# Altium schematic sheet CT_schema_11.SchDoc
size 281 x 153 mm
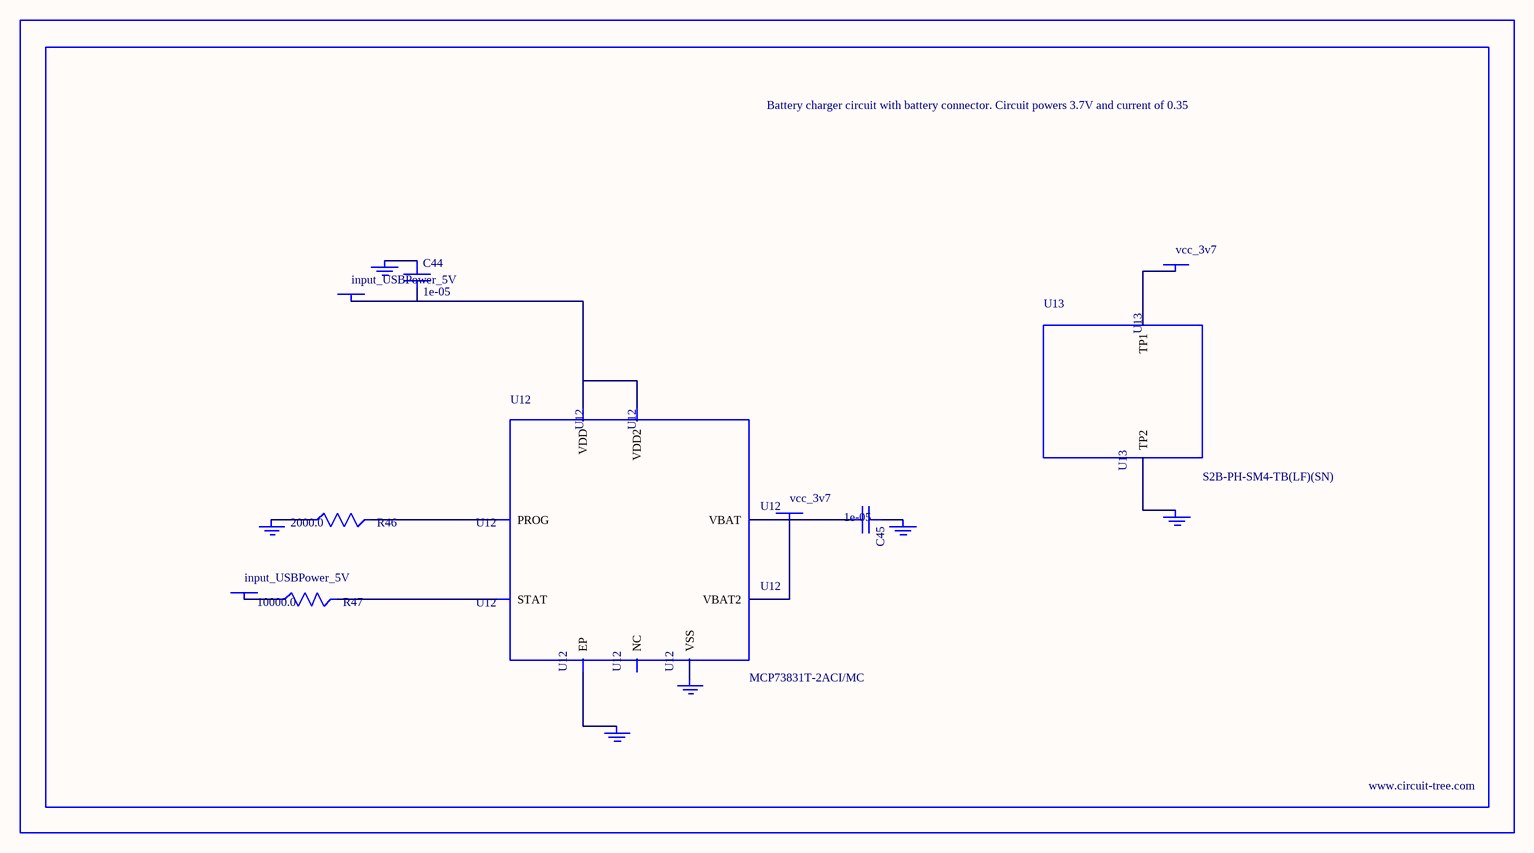
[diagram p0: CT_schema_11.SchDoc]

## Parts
BORDER10  (no value)
C44  1e-05  [C1206]
C45  1e-05  [C1206]
GND_INSTANCE_10_0  (no value)
GND_INSTANCE_10_1  (no value)
GND_INSTANCE_10_2  (no value)
GND_INSTANCE_10_3  (no value)
GND_INSTANCE_10_4  (no value)
GND_INSTANCE_10_5  (no value)
POWER_INSTANCE_10_0  input_USBPower_5V
POWER_INSTANCE_10_1  input_USBPower_5V
POWER_INSTANCE_10_2  vcc_3v7
POWER_INSTANCE_10_3  vcc_3v7
R46  2000.0  [R0603]
R47  10000.0  [R0603]
U12  MCP73831T-2ACI/MC  [DFN8_2X3MC]
U13  S2B-PH-SM4-TB(LF)(SN)  [JST-2-SMD]

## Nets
NetC44_1: C44.1 GND_INSTANCE_10_0.0(GND)
NetC44_2: C44.2 POWER_INSTANCE_10_0.0(PWR) U12.1(VDD) U12.2(VDD2)
NetC45_1: C45.1 GND_INSTANCE_10_1.0(GND)
NetC45_2: C45.2 POWER_INSTANCE_10_2.0(PWR) U12.3(VBAT) U12.4(VBAT2)
NetGND_INSTANCE_10_2_0: GND_INSTANCE_10_2.0(GND) R46.1
NetGND_INSTANCE_10_3_0: GND_INSTANCE_10_3.0(GND) U12.9(EP)
NetGND_INSTANCE_10_4_0: GND_INSTANCE_10_4.0(GND) U12.6(VSS)
NetGND_INSTANCE_10_5_0: GND_INSTANCE_10_5.0(GND) U13.2(TP2)
NetPOWER_INSTANCE_10_1_0: POWER_INSTANCE_10_1.0(PWR) R47.1
NetPOWER_INSTANCE_10_3_0: POWER_INSTANCE_10_3.0(PWR) U13.1(TP1)
NetR46_2: R46.2 U12.8(PROG)
NetR47_2: R47.2 U12.5(STAT)

Not connected (* = marked no-connect by the designer): U12 7(NC)

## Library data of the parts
BORDER10 = BORDER_PAGE10
C44 C45 = C1206C106K3RACTU
GND_INSTANCE_10_0-GND_INSTANCE_10_5 = GND
POWER_INSTANCE_10_0-POWER_INSTANCE_10_3 = PWR
R46 = RC0603JR-072KL
R47 = RC0603JR-0710KL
